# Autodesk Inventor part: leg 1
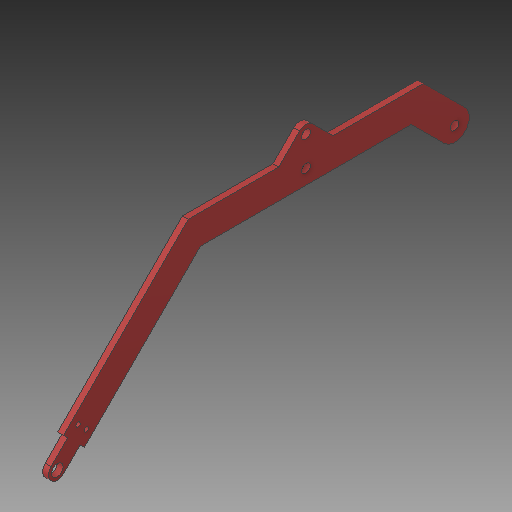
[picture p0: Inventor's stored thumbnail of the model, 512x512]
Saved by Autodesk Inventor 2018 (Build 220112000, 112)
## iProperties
Created: 2023-12
Part Number: leg 1
Material: Generic
Document SubType Name: Modeling
Designer: DDUGKY
Density: 1 g/cm^3
Appearance: Default
Author: DDUGKY
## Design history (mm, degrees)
sketch "Sketch1"
  geometry: L1 (-212.132, 212.132)-(-219.203, 205.061); L2 (-247.487, 176.777)-(-240.416, 183.848); L3 (-219.203, 205.061)-(-247.487, 233.345); L4 (-240.416, 183.848)-(-268.701, 212.132); L5 (0, 0)-(300, 0); L6 (0, -400)-(-70.711, -470.711); L7 (-106.066, -435.355)-(-50, -379.289); L8 (-50, -379.289)-(-50, -20.711); L9 (-50, -20.711)-(-247.487, 176.777); L10 (0, 0)-(-212.132, 212.132); L11 (35.314, -189.101)-(0, -153.787); L12 (35.607, -210.607)-(0, -246.213); L13 (0, 0)-(0, -153.787); L14 (0, -246.213)-(0, -400); C1 r 10 at (-258.094, 222.739); C2 r 7.5 at (-88.388, -453.033); C3 r 7.5 at (25, -200); C4 r 7.5 at (-25, -200); A1 r 15 centre (-258.094, 222.739) between (-247.487, 233.345) and (-268.701, 212.132); A2 r 25 centre (-88.388, -453.033) between (-106.066, -435.355) and (-70.711, -470.711); A3 r 15.419 centre (24.411, -200.004) between (35.607, -210.607) and (35.314, -189.101)
  constraints: 28 end point, 7 centre point, 6 point on circle, 1 coincident, 1 collinear, 1 point on line, 1 tangent, 1 vertical
  dimensions: "d1" = 400 distance of L5.start L6.start; "d11" = 20 diameter of C1; "d25" = 10 distance of L1.start L1.end; "d26" = 10 distance of L2.start L2.end; "d31" = 100 distance of L6.start L6.end; "d33" = 15 diameter of C2; "d46" = 15 diameter of C3; "d52" = 15 diameter of C4
sketch "Sketch3"
  geometry: L1 (-258.094, 222.739)-(-215.668, 180.312); L2 (-258.094, 222.739)-(-198.094, 222.739); L3 (-215.668, 180.312)-(-222.739, 173.241); L4 (-215.668, 180.312)-(-208.597, 187.383); C1 r 6.25 at (-258.094, 222.739) reference; C2 r 3.75 at (-208.597, 187.383); C3 r 3.75 at (-222.739, 173.241); 1 further point
  constraints: 8 end point, 2 centre point, 2 coincident, 1 equal length, 1 horizontal, 1 perpendicular
  dimensions: "d37" = 60 distance of L1.start L1.end; "d38" = 45 deg angle of L1 L2; "d39" = 10 distance of L1.end L3.end; "d40" = 10 distance of L1.end L4.end; "d41" = 7.5 diameter of C2; "d42" = 7.5 diameter of C3
extrude "Extrusion8" join sketch "Sketch1" stored distance "d53" = 10; taper "d54" = 0 deg
extrude "Extrusion9" cut sketch "Sketch3" stored distance "d55" = 47; taper "d56" = 0 deg
body "Solid3"
